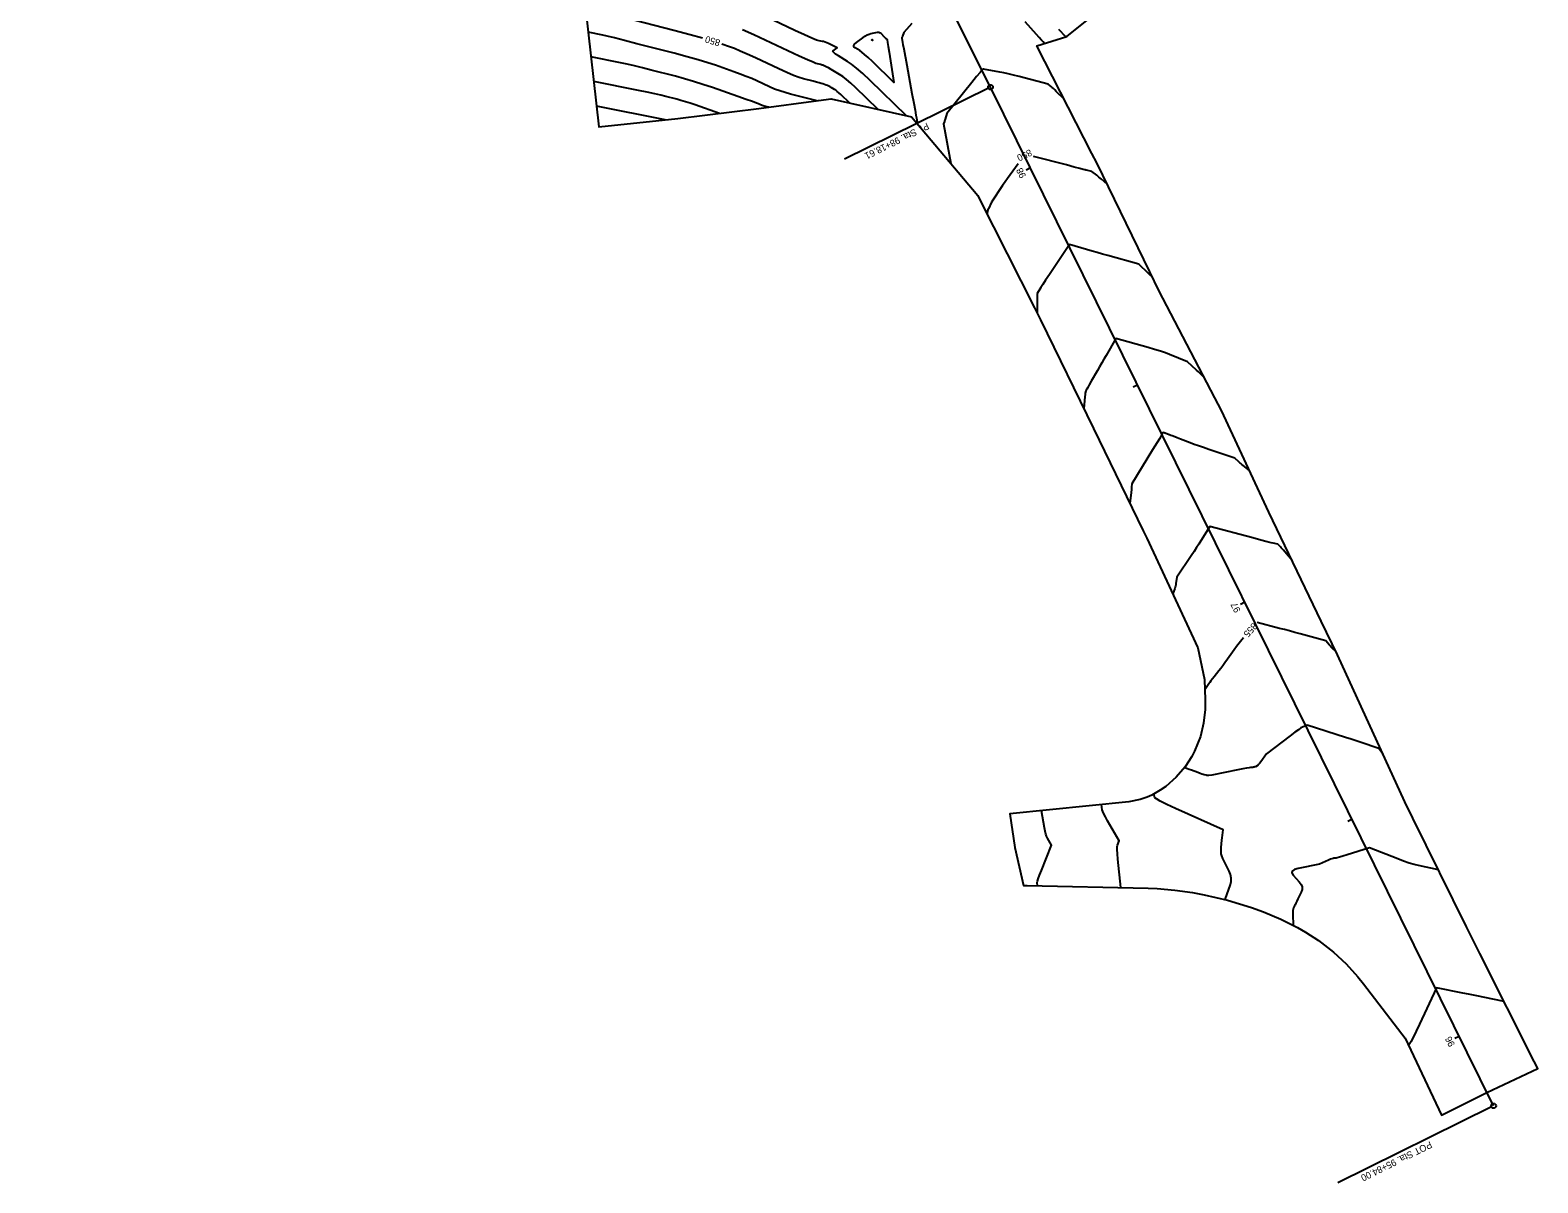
# Model space of a CAD drawing. Extents: x 1715724 to 1716561, y 394063 to 395906.
# Drawn here: x 1716249.5 to 1716560.8, y 394062.8 to 394300.9 of the extents above; entities that cross this region are included whole.
import ezdxf

# ---------------------------------------------------------------- set-up
doc = ezdxf.new("R2010")
doc.units = 0
for name, color, linetype in [('DT_X_Contour_Major', 7, 'Continuous'), ('DT_X_Contour_Minor', 7, 'Continuous'), ('DT_X_TIN_Hull', 7, 'Continuous'), ('GE_P_CL_10', 7, 'Continuous')]:
    doc.layers.add(name, color=color, linetype=linetype)

msp = doc.modelspace()

# ---------------------------------------------------------------- linework, layer by layer
at = {"layer": 'DT_X_Contour_Major'}
for points in [[(1716388.29, 394299.2), (1716385.79, 394299.87), (1716382.38, 394300.77), (1716372.3, 394303.38), (1716368.98, 394304.24), (1716366.59, 394304.87), (1716365.13, 394305.25), (1716364.6, 394305.4), (1716364.42, 394305.49), (1716364.35, 394305.52), (1716364.3, 394305.55), (1716364.24, 394305.58), (1716363.99, 394305.73)], [(1716418.72, 394285.8), (1716416.88, 394287.58), (1716416.5, 394287.93), (1716416.16, 394288.23), (1716415.86, 394288.46), (1716415.59, 394288.64), (1716414.91, 394289.03), (1716414.66, 394289.17), (1716414.4, 394289.3), (1716414.14, 394289.42), (1716413.88, 394289.52), (1716413.17, 394289.77), (1716412.84, 394289.87), (1716412.4, 394290), (1716411.83, 394290.15), (1716411.15, 394290.33), (1716409.16, 394290.82), (1716408.28, 394291.08), (1716407.14, 394291.51), (1716405.73, 394292.11), (1716404.06, 394292.87), (1716399.24, 394295.13), (1716397.56, 394295.9), (1716396.11, 394296.54), (1716394.9, 394297.05), (1716393.92, 394297.41), (1716392.31, 394297.98)], [(1716471.9, 394269.04), (1716470.69, 394270.1), (1716470.44, 394270.32), (1716470.19, 394270.52), (1716469.96, 394270.71), (1716469.74, 394270.89), (1716468.72, 394271.66), (1716467.89, 394271.87), (1716467.6, 394271.94), (1716467.49, 394271.97), (1716467.42, 394271.99), (1716467.26, 394272.03), (1716466.97, 394272.1), (1716466.25, 394272.29), (1716465.08, 394272.6), (1716463.47, 394273.02), (1716456.65, 394274.79)], [(1716453.5, 394273.29), (1716452.38, 394271.75), (1716451.84, 394271), (1716451.32, 394270.26), (1716450.8, 394269.52), (1716450.3, 394268.78), (1716447.99, 394265.33), (1716447.4, 394264), (1716447.28, 394263.74), (1716447.2, 394263.53), (1716447.16, 394263.36), (1716447.14, 394263.24), (1716447.14, 394262.79)], [(1716519.11, 394172.58), (1716518.46, 394173.19), (1716518.32, 394173.33), (1716518.17, 394173.48), (1716518.01, 394173.65), (1716517.84, 394173.84), (1716517.03, 394174.74), (1716511.75, 394176.2), (1716510.64, 394176.5), (1716509.56, 394176.79), (1716508.52, 394177.07), (1716507.51, 394177.33), (1716502.89, 394178.52), (1716502.88, 394178.52)], [(1716500.08, 394175.4), (1716499.7, 394174.96), (1716499.15, 394174.3), (1716498.62, 394173.61), (1716498.09, 394172.89), (1716496.72, 394170.94), (1716496.22, 394170.25), (1716495.76, 394169.62), (1716495.34, 394169.06), (1716494.95, 394168.57), (1716493.97, 394167.35), (1716493.63, 394166.91), (1716493.33, 394166.52), (1716493.08, 394166.18), (1716492.88, 394165.89), (1716492.06, 394164.62)]]:
    msp.add_lwpolyline(points, dxfattribs=at)
at = {"layer": 'DT_X_Contour_Minor'}
for points in [[(1716430.44, 394283.18), (1716422.93, 394290.47), (1716421.43, 394291.88), (1716420.15, 394293.02), (1716419.11, 394293.86), (1716418.28, 394294.42), (1716416.39, 394295.53), (1716415.79, 394295.91), (1716415.41, 394296.22), (1716415.26, 394296.45), (1716415.32, 394296.62), (1716416.15, 394297.23), (1716414.35, 394298.11), (1716413.98, 394298.28), (1716413.64, 394298.41), (1716413.34, 394298.5), (1716413.07, 394298.55), (1716412.39, 394298.64), (1716411.89, 394298.8), (1716410.89, 394299.22), (1716409.4, 394299.89), (1716407.41, 394300.81), (1716401.45, 394303.6)], [(1716458.96, 394298.13), (1716458.67, 394298.42), (1716458.6, 394298.5), (1716458.52, 394298.59), (1716458.42, 394298.7), (1716458.31, 394298.83), (1716457.84, 394299.38), (1716457.3, 394299.98), (1716454.97, 394302.61)], [(1716412.03, 394286.29), (1716406.52, 394287.65), (1716405.37, 394287.96), (1716404.26, 394288.31), (1716403.2, 394288.71), (1716402.19, 394289.15), (1716399.55, 394290.39), (1716398.51, 394290.85), (1716397.37, 394291.32), (1716396.11, 394291.81), (1716394.76, 394292.29), (1716391, 394293.61), (1716389.41, 394294.13), (1716387.45, 394294.72), (1716385.13, 394295.37), (1716382.44, 394296.08), (1716374.77, 394298.07), (1716372.18, 394298.74), (1716370.14, 394299.25), (1716368.66, 394299.61), (1716367.73, 394299.82), (1716364.72, 394300.42)], [(1716424.58, 394284.49), (1716419.9, 394289.02), (1716418.94, 394289.92), (1716418.08, 394290.67), (1716417.3, 394291.27), (1716416.61, 394291.72), (1716414.9, 394292.72), (1716414.33, 394293.05), (1716413.89, 394293.3), (1716413.59, 394293.46), (1716413.43, 394293.53), (1716413.17, 394293.63), (1716413.06, 394293.66), (1716412.89, 394293.71), (1716412.69, 394293.77), (1716412.44, 394293.83), (1716411.72, 394294.01), (1716411.16, 394294.22), (1716410, 394294.72), (1716408.26, 394295.51), (1716405.93, 394296.59), (1716398.94, 394299.87), (1716396.6, 394300.96)], [(1716421.41, 394299.3), (1716421.88, 394299.63), (1716422.32, 394299.88), (1716422.73, 394300.07), (1716423.11, 394300.19), (1716424.09, 394300.4), (1716424.43, 394300.45), (1716424.74, 394300.42), (1716425.01, 394300.31), (1716425.24, 394300.14), (1716425.8, 394299.57), (1716425.99, 394299.38), (1716426.14, 394299.24), (1716426.24, 394299.15), (1716426.29, 394299.1), (1716426.38, 394299.03), (1716426.44, 394298.85), (1716426.54, 394298.33), (1716426.69, 394297.48), (1716426.87, 394296.31), (1716427.85, 394290.06), (1716423.41, 394294.37), (1716422.54, 394295.2), (1716421.81, 394295.85), (1716421.23, 394296.33), (1716420.8, 394296.63), (1716419.84, 394297.19), (1716419.59, 394297.42), (1716419.55, 394297.68), (1716419.72, 394297.99), (1716420.1, 394298.33), (1716421.41, 394299.3)], [(1716431.56, 394302.23), (1716429.88, 394300.35), (1716429.6, 394299.63), (1716429.54, 394299.49), (1716429.51, 394299.39), (1716429.48, 394299.31), (1716429.47, 394299.27), (1716429.46, 394299.19), (1716429.46, 394299.16), (1716429.46, 394299.15), (1716429.47, 394299.13), (1716429.47, 394299.12), (1716429.5, 394299.11), (1716429.51, 394299.08), (1716429.52, 394299.02), (1716429.54, 394298.91), (1716429.56, 394298.77), (1716429.63, 394298.33), (1716429.71, 394297.91), (1716429.87, 394296.98), (1716430.49, 394293.61), (1716431.57, 394287.75), (1716431.94, 394285.79), (1716432.21, 394284.31), (1716432.39, 394283.31), (1716432.49, 394282.79), (1716432.73, 394281.48)], [(1716463.38, 394299.47), (1716461.89, 394300.99)], [(1716423.32, 394298.88), (1716423.34, 394298.89), (1716423.34, 394298.89), (1716423.36, 394298.9), (1716423.37, 394298.9), (1716423.38, 394298.89), (1716423.38, 394298.88), (1716423.39, 394298.88), (1716423.39, 394298.88), (1716423.39, 394298.88), (1716423.39, 394298.88), (1716423.39, 394298.88), (1716423.39, 394298.87), (1716423.4, 394298.87), (1716423.4, 394298.85), (1716423.4, 394298.83), (1716423.42, 394298.74), (1716423.35, 394298.8), (1716423.33, 394298.82), (1716423.32, 394298.83), (1716423.31, 394298.83), (1716423.31, 394298.84), (1716423.29, 394298.85), (1716423.29, 394298.85), (1716423.29, 394298.86), (1716423.29, 394298.86), (1716423.3, 394298.87), (1716423.32, 394298.88)], [(1716402.01, 394284.94), (1716401.06, 394285.17), (1716400.86, 394285.23), (1716400.67, 394285.29), (1716400.49, 394285.36), (1716400.31, 394285.43), (1716399.86, 394285.64), (1716399.46, 394285.8), (1716398.62, 394286.11), (1716397.33, 394286.56), (1716395.59, 394287.18), (1716390.36, 394289), (1716388.41, 394289.67), (1716386.49, 394290.28), (1716384.59, 394290.83), (1716382.71, 394291.34), (1716377.75, 394292.63), (1716375.96, 394293.08), (1716374.3, 394293.48), (1716372.78, 394293.83), (1716371.4, 394294.12), (1716365.28, 394295.34)], [(1716391.81, 394283.67), (1716386.83, 394285.41), (1716385.78, 394285.77), (1716384.8, 394286.08), (1716383.87, 394286.36), (1716382.99, 394286.6), (1716380.73, 394287.19), (1716379.74, 394287.43), (1716378.46, 394287.72), (1716376.91, 394288.04), (1716375.07, 394288.42), (1716365.85, 394290.26)], [(1716463.04, 394286.61), (1716461.39, 394288.22), (1716461.06, 394288.54), (1716460.78, 394288.8), (1716460.56, 394289), (1716460.39, 394289.14), (1716459.7, 394289.68), (1716453.75, 394291.26), (1716452.55, 394291.57), (1716451.47, 394291.83), (1716450.54, 394292.04), (1716449.74, 394292.2), (1716447.14, 394292.67), (1716446.68, 394292.75), (1716446.4, 394292.8), (1716446.29, 394292.82), (1716446.28, 394292.82), (1716446.27, 394292.82), (1716446.26, 394292.82), (1716446.25, 394292.82), (1716446.22, 394292.83), (1716446.2, 394292.82), (1716446.2, 394292.82), (1716446.19, 394292.81), (1716446.19, 394292.81), (1716446.19, 394292.81), (1716446.19, 394292.81), (1716446.05, 394292.64), (1716445.64, 394292.12), (1716444.94, 394291.26), (1716443.97, 394290.06), (1716438.79, 394283.62), (1716438.43, 394282.46), (1716438.37, 394282.29), (1716438.32, 394282.15), (1716438.28, 394282.02), (1716438.09, 394281.51), (1716439.6, 394273.31)], [(1716380.6, 394282.35), (1716366.41, 394285.18)], [(1716481.22, 394249.89), (1716480.96, 394250.14), (1716480.87, 394250.23), (1716480.45, 394250.62), (1716478.45, 394252.51), (1716472, 394254.32), (1716470.91, 394254.62), (1716469.85, 394254.93), (1716468.82, 394255.22), (1716464.11, 394256.59), (1716459.98, 394250.43), (1716459.19, 394249.25), (1716458.59, 394248.35), (1716458.19, 394247.74), (1716457.98, 394247.4), (1716457.45, 394246.51), (1716457.45, 394244.46), (1716457.45, 394244.14), (1716457.45, 394243.85), (1716457.45, 394243.58), (1716457.47, 394242.38)], [(1716491.95, 394229.14), (1716491.4, 394229.7), (1716491.25, 394229.85), (1716491.03, 394230.06), (1716490.74, 394230.33), (1716490.37, 394230.66), (1716488.51, 394232.34), (1716484.79, 394233.86), (1716483.92, 394234.2), (1716482.88, 394234.55), (1716481.69, 394234.92), (1716480.34, 394235.31), (1716473.68, 394237.17), (1716471.67, 394233.69), (1716471.24, 394232.93), (1716470.79, 394232.16), (1716470.34, 394231.36), (1716469.87, 394230.55), (1716468.62, 394228.36), (1716468.21, 394227.63), (1716467.91, 394227.1), (1716467.71, 394226.76), (1716467.56, 394226.49), (1716467.54, 394226.45), (1716467.52, 394226.41), (1716467.5, 394226.38), (1716467.48, 394226.35), (1716467.4, 394226.21), (1716467.4, 394226.19), (1716467.39, 394226.13), (1716467.37, 394225.93), (1716467.34, 394225.6), (1716467.29, 394225.14), (1716467.06, 394222.71)], [(1716501.29, 394209.94), (1716499.98, 394210.95), (1716499.71, 394211.16), (1716499.47, 394211.36), (1716499.26, 394211.55), (1716499.08, 394211.72), (1716498.29, 394212.49), (1716492.9, 394214.28), (1716491.79, 394214.65), (1716490.78, 394215), (1716489.87, 394215.33), (1716489.06, 394215.63), (1716487.03, 394216.4), (1716486.35, 394216.66), (1716485.84, 394216.86), (1716485.3, 394217.07), (1716485.02, 394217.18), (1716484.91, 394217.22), (1716484.8, 394217.27), (1716484.67, 394217.32), (1716484.53, 394217.38), (1716484.02, 394217.59), (1716483.91, 394217.63), (1716483.81, 394217.66), (1716483.74, 394217.69), (1716483.43, 394217.77), (1716483.2, 394217.37), (1716483.04, 394217.11), (1716482.67, 394216.5), (1716481.28, 394214.2), (1716477.02, 394207.21), (1716476.95, 394206.52), (1716476.94, 394206.33), (1716476.91, 394206.07), (1716476.82, 394205.32), (1716476.56, 394203.22)], [(1716510.08, 394191.36), (1716508.59, 394193.14), (1716508.29, 394193.49), (1716508.05, 394193.77), (1716507.85, 394193.99), (1716507.71, 394194.14), (1716507.15, 394194.69), (1716506.17, 394194.9), (1716505.75, 394195.01), (1716504.91, 394195.22), (1716503.65, 394195.56), (1716501.96, 394196), (1716493.1, 394198.36), (1716491.27, 394195.41), (1716490.85, 394194.74), (1716490.37, 394194), (1716489.83, 394193.18), (1716489.23, 394192.28), (1716486.29, 394187.93), (1716486.11, 394186.62), (1716486.07, 394186.35), (1716486.01, 394186.08), (1716485.94, 394185.82), (1716485.86, 394185.58), (1716485.44, 394184.45)], [(1716528.89, 394151.29), (1716527.97, 394152.54), (1716524.18, 394153.8), (1716523.3, 394154.09), (1716522.27, 394154.43), (1716521.09, 394154.82), (1716513.21, 394157.36), (1716512.23, 394156.95), (1716511.92, 394156.77), (1716511.39, 394156.41), (1716510.66, 394155.87), (1716509.71, 394155.16), (1716504.8, 394151.42), (1716503.62, 394149.77), (1716503.38, 394149.45), (1716503.18, 394149.21), (1716503.01, 394149.03), (1716502.87, 394148.94), (1716502.53, 394148.77), (1716502.41, 394148.71), (1716502.27, 394148.67), (1716502.12, 394148.64), (1716501.96, 394148.62), (1716501.52, 394148.6), (1716501.24, 394148.56), (1716500.7, 394148.46), (1716499.92, 394148.32), (1716498.9, 394148.11), (1716493.53, 394147.04), (1716492.91, 394146.95), (1716492.77, 394146.94), (1716492.63, 394146.94), (1716492.49, 394146.96), (1716492.34, 394146.99), (1716491.93, 394147.1), (1716491.74, 394147.15), (1716491.46, 394147.25), (1716491.08, 394147.37), (1716490.63, 394147.54), (1716489.28, 394148.03), (1716488.83, 394148.19), (1716488.49, 394148.32), (1716488.26, 394148.41), (1716488.14, 394148.46), (1716487.82, 394148.6)], [(1716474.73, 394123.79), (1716474.13, 394129.67), (1716474.03, 394130.79), (1716473.98, 394131.65), (1716473.97, 394132.24), (1716474.03, 394132.57), (1716474.38, 394133.46), (1716471.99, 394137.59), (1716471.54, 394138.4), (1716471.2, 394139.04), (1716470.99, 394139.52), (1716470.89, 394139.84), (1716470.71, 394140.95)], [(1716496.26, 394121.32), (1716497.36, 394124.42), (1716497.52, 394125.09), (1716497.53, 394125.78), (1716497.39, 394126.48), (1716497.1, 394127.2), (1716496.12, 394129.14), (1716495.8, 394129.81), (1716495.58, 394130.36), (1716495.45, 394130.8), (1716495.41, 394131.13), (1716495.44, 394131.86), (1716495.45, 394132.12), (1716495.47, 394132.37), (1716495.49, 394132.6), (1716495.51, 394132.82), (1716495.61, 394133.58), (1716495.66, 394134.07), (1716495.83, 394135.7), (1716486.04, 394140.13), (1716484.2, 394140.98), (1716482.87, 394141.64), (1716482.06, 394142.1), (1716481.75, 394142.36), (1716481.54, 394143.14)], [(1716457.5, 394124.19), (1716457.43, 394124.83), (1716457.48, 394125.1), (1716457.64, 394125.6), (1716457.91, 394126.35), (1716458.3, 394127.35), (1716460.37, 394132.58), (1716459.54, 394134.03), (1716459.37, 394134.39), (1716459.21, 394134.87), (1716459.06, 394135.46), (1716458.93, 394136.16), (1716458.35, 394139.68)], [(1716540.32, 394127.44), (1716536.2, 394128.35), (1716535.27, 394128.58), (1716534.25, 394128.88), (1716533.13, 394129.26), (1716531.92, 394129.71), (1716526.06, 394131.99), (1716521.44, 394130.54), (1716520.56, 394130.27), (1716519.88, 394130.07), (1716519.42, 394129.95), (1716519.16, 394129.9), (1716518.74, 394129.86), (1716518.56, 394129.83), (1716518.31, 394129.76), (1716518, 394129.64), (1716517.64, 394129.49), (1716515.78, 394128.66), (1716511.32, 394127.76), (1716510.55, 394127.53), (1716510.12, 394127.22), (1716510.06, 394126.82), (1716510.34, 394126.35), (1716511.58, 394124.98), (1716511.95, 394124.47), (1716512.15, 394123.95), (1716512.16, 394123.42), (1716511.99, 394122.89), (1716511.29, 394121.46), (1716511.05, 394120.97), (1716510.85, 394120.57), (1716510.7, 394120.27), (1716510.6, 394120.05), (1716510.37, 394119.59), (1716510.3, 394119.38), (1716510.26, 394119.09), (1716510.24, 394118.72), (1716510.24, 394118.28), (1716510.31, 394116.02)], [(1716553.87, 394100.26), (1716549.55, 394101.17), (1716548.59, 394101.37), (1716547.58, 394101.58), (1716546.5, 394101.79), (1716545.36, 394102.02), (1716539.9, 394103.1), (1716536.39, 394095.6), (1716535.72, 394094.17), (1716535.21, 394093.1), (1716534.85, 394092.38), (1716534.66, 394092.03), (1716534.13, 394091.19)]]:
    msp.add_lwpolyline(points, dxfattribs=at)
at = {"layer": 'DT_X_TIN_Hull'}
msp.add_lwpolyline([(1716364.18, 394305.34), (1716366.88, 394280.88), (1716383.22, 394282.63), (1716399.92, 394284.66), (1716412.31, 394286.32), (1716414.92, 394286.65), (1716431.5, 394282.95), (1716445.15, 394266.71), (1716445.6, 394265.82), (1716456.9, 394243.55), (1716458.13, 394241.03), (1716469.07, 394218.58), (1716479.36, 394197.48), (1716480.08, 394195.94), (1716490.63, 394173.31), (1716491.97, 394166.76), (1716492.15, 394162.58), (1716492.1, 394160.6), (1716491.8, 394157.75), (1716491.16, 394155), (1716489.95, 394151.97), (1716489.36, 394150.88), (1716487.97, 394148.77), (1716486.12, 394146.59), (1716484, 394144.71), (1716482.86, 394143.89), (1716481.1, 394142.89), (1716480.17, 394142.47), (1716478.72, 394141.97), (1716476.37, 394141.53), (1716451.81, 394139.01), (1716452.82, 394132.11), (1716454.61, 394124.26), (1716455.38, 394124.24), (1716480.33, 394123.66), (1716482.2, 394123.59), (1716485.9, 394123.29), (1716489.54, 394122.78), (1716491.95, 394122.34), (1716496.73, 394121.21), (1716501.71, 394119.71), (1716504.16, 394118.82), (1716507.75, 394117.31), (1716511.22, 394115.56), (1716512.89, 394114.59), (1716515.52, 394112.87), (1716516.79, 394111.94), (1716518.63, 394110.45), (1716521.24, 394108.03), (1716523.68, 394105.35), (1716524.83, 394103.91), (1716533.43, 394092.68), (1716540.94, 394076.8), (1716550.33, 394081.5), (1716560.84, 394086.42), (1716560.1, 394087.89), (1716548.85, 394110.2), (1716546.12, 394115.72), (1716535.04, 394138.11), (1716533.38, 394141.5), (1716519.46, 394171.85), (1716516.1, 394178.84), (1716505.29, 394201.35), (1716495.52, 394222.32), (1716494.13, 394224.97), (1716482.56, 394247.11), (1716480.68, 394250.99), (1716469.76, 394273.45), (1716468.76, 394275.41), (1716457.4, 394297.65), (1716463.55, 394299.53), (1716471.86, 394306.26)], dxfattribs=at)
at = {"layer": 'GE_P_CL_10'}
for p, q in [((1716447.81, 394289.08), (1716249.46, 394685.42)), ((1716447.36, 394288.86), (1716417.65, 394274.19)), ((1716551.7, 394078.73), (1716447.81, 394289.08)), ((1716456.05, 394272.4), (1716455.15, 394271.95)), ((1716478.19, 394227.57), (1716477.29, 394227.12)), ((1716500.33, 394182.73), (1716499.43, 394182.29)), ((1716522.47, 394137.9), (1716521.58, 394137.46)), ((1716544.61, 394093.07), (1716543.72, 394092.63)), ((1716551.25, 394078.51), (1716519.52, 394062.83))]:
    msp.add_line(p, q, dxfattribs=at)
for centre in [(1716447.81, 394289.08), (1716551.7, 394078.73)]:
    msp.add_circle(centre, 0.5, dxfattribs=at)

# ---------------------------------------------------------------- texts
at = {"layer": 'DT_X_Contour_Major'}
for s, rotation, p in [('850', 163.1184, (1716392.1, 394298.82)), ('850', 205.445, (1716455.93, 394276.33)), ('855', 228.0535, (1716502.02, 394178.61))]:
    msp.add_text(s, height=1.4, rotation=rotation, dxfattribs=at).set_placement(p)
at = {"layer": 'GE_P_CL_10'}
for s, rotation, p in [('PI  Sta. 98+18.61', 206.2838, (1716434.67, 394281.81)), ('98', 116.2838, (1716455.2, 394270.72)), ('97', 116.2838, (1716499.51, 394181.01)), ('96', 116.2838, (1716543.78, 394091.37)), ('POT Sta. 95+84.00', 206.2838, (1716538.56, 394071.46))]:
    msp.add_text(s, height=1.4, rotation=rotation, dxfattribs=at).set_placement(p)

doc.saveas('drawing.dxf')
